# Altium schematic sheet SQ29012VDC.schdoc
size 127 x 101 mm
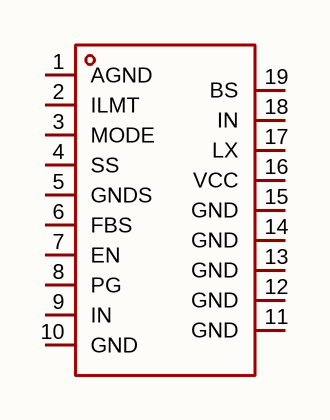
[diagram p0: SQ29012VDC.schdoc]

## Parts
U?  sq29012vdc  [QFN-19_L4.0-W3.0-P0.50-TL]  (value not drawn)

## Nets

Not connected (* = marked no-connect by the designer): U? 1(AGND) 2(ILMT) 3(MODE) 4(SS) 5(GNDS) 6(FBS) 7(EN) 8(PG) 9(IN) 10(GND) 11(GND) 12(GND) 13(GND) 14(GND) 15(GND) 16(VCC) 17(LX) 18(IN) 19(BS)

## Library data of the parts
U? = sq29012vdc: 功能类型:降压型;工作电压:2.7V~16V;输出电压:600mV~5.5V;输出电流:12A;输出类型:可调;; Manufacturer: Silergy(矽力杰); AddInBom: yes; Function: 降压型; Output Current: 12A; Frequency - Switching: 600kHz；1MHz；800kHz; Synchronous Rectifier: 是; Number of Outputs: 1; Topology: 降压式; Quiescent Current: 650uA; Switch tube (built-in/external): 内置; Output Type: 可调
